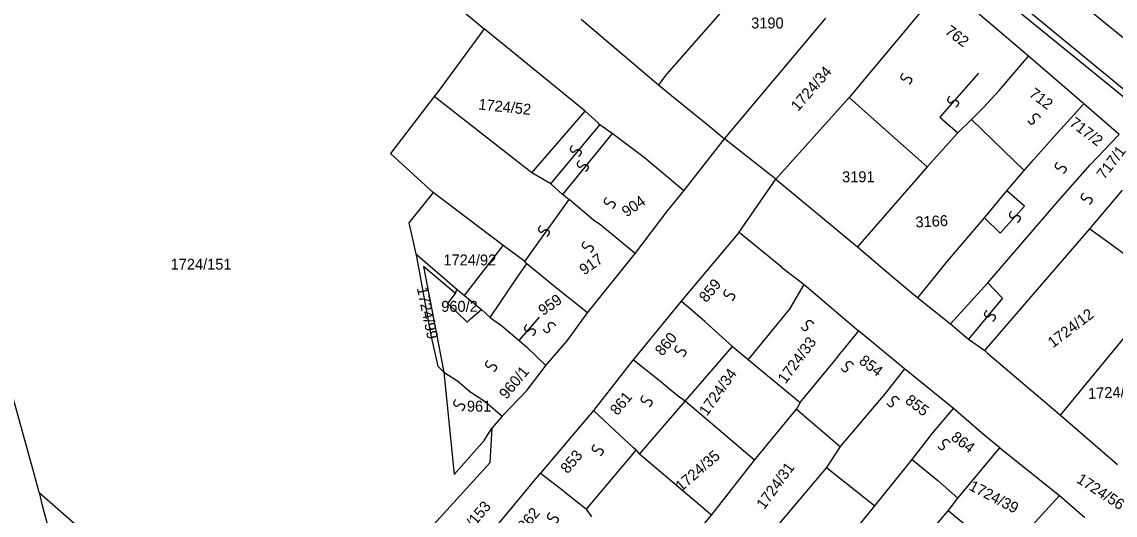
# Model space of a CAD drawing. Extents: x -581999 to -572728, y -1219553 to -1212032.
# Drawn here: x -578552 to -578351.7, y -1215656.3 to -1215566 of the extents above; entities that cross this region are included whole.
import ezdxf

# ---------------------------------------------------------------- set-up
doc = ezdxf.new("R2010")
doc.units = 0
for name, color, linetype in [('Vrstva 1', 7, 'Continuous'), ('Vrstva 2', 7, 'Continuous'), ('Vrstva 4', 7, 'Continuous'), ('Vrstva 6', 7, 'Continuous')]:
    doc.layers.add(name, color=color, linetype=linetype)

msp = doc.modelspace()

# ---------------------------------------------------------------- linework, layer by layer
at = {"layer": 'Vrstva 1'}
for p, q in [((-578500.138, -1215539.76), (-578467.315, -1215567.303)), ((-578430.775, -1215596.918), (-578423.284, -1215587.415)), ((-578413.904, -1215594.804), (-578423.284, -1215587.415)), ((-578420.638, -1215604.474), (-578413.904, -1215594.804)), ((-578470.898, -1215616.085), (-578463.835, -1215606.894)), ((-578472.578, -1215615.681), (-578478.448, -1215610.76)), ((-578478.448, -1215610.76), (-578474.701, -1215630.091)), ((-578473.952, -1215617.555), (-578472.578, -1215615.681)), ((-578472.578, -1215615.681), (-578472.313, -1215614.94)), ((-578470.455, -1215620.953), (-578473.952, -1215617.555)), ((-578469.83, -1215620.367), (-578470.455, -1215620.953)), ((-578469.83, -1215620.367), (-578467.832, -1215618.61)), ((-578474.701, -1215630.091), (-578472.828, -1215648.836)), ((-578467.332, -1215642.627), (-578465.871, -1215640.298)), ((-578472.828, -1215648.836), (-578467.332, -1215642.627)), ((-578548.825, -1215652.118), (-578520.198, -1215677.165))]:
    msp.add_line(p, q, dxfattribs=at)
for points in [[(-578433.992, -1215511.611), (-578315.4, -1215607.929)], [(-578416.974, -1215556.238), (-578433.877, -1215575.53)], [(-578367.591, -1215572.29), (-578383.131, -1215559.047), (-578400.453, -1215579.858)], [(-578449.558, -1215565.489), (-578435.404, -1215577.522)], [(-578423.284, -1215587.415), (-578404.758, -1215565.353)], [(-578448.816, -1215582.341), (-578467.315, -1215567.303), (-578475.737, -1215578.764), (-578476.49, -1215579.668)], [(-578372.982, -1215578.582), (-578367.591, -1215572.29)], [(-578357.461, -1215580.996), (-578367.591, -1215572.29)], [(-578433.877, -1215575.53), (-578435.404, -1215577.522)], [(-578435.404, -1215577.522), (-578432.98, -1215579.481)], [(-578476.49, -1215579.668), (-578484.46, -1215590.07), (-578476.638, -1215597.204)], [(-578458.591, -1215593.643), (-578476.49, -1215579.668)], [(-578432.98, -1215579.481), (-578425.998, -1215585.162)], [(-578413.904, -1215594.804), (-578400.453, -1215579.858)], [(-578400.453, -1215579.858), (-578395.957, -1215583.883)], [(-578375.84, -1215581.698), (-578372.982, -1215578.582)], [(-578458.591, -1215593.643), (-578448.816, -1215582.341)], [(-578446.111, -1215584.816), (-578446.411, -1215584.466), (-578448.816, -1215582.341)], [(-578378.026, -1215583.887), (-578375.84, -1215581.698)], [(-578362.916, -1215586.976), (-578357.461, -1215580.996)], [(-578350.995, -1215586.596), (-578357.461, -1215580.996)], [(-578395.957, -1215583.883), (-578386.17, -1215592.501)], [(-578380.548, -1215586.328), (-578378.026, -1215583.887)], [(-578368.381, -1215593.208), (-578378.026, -1215583.887)], [(-578443.855, -1215586.441), (-578446.111, -1215584.816)], [(-578437.991, -1215590.846), (-578443.855, -1215586.441)], [(-578425.998, -1215585.162), (-578423.284, -1215587.415)], [(-578386.17, -1215592.501), (-578380.548, -1215586.328)], [(-578366.699, -1215591.271), (-578362.916, -1215586.976)], [(-578356.288, -1215592.14), (-578350.995, -1215586.596)], [(-578439.646, -1215608.372), (-578433.733, -1215600.568), (-578430.775, -1215596.918), (-578437.991, -1215590.846)], [(-578368.381, -1215593.208), (-578366.699, -1215591.271)], [(-578362.225, -1215598.896), (-578356.288, -1215592.14)], [(-578455.133, -1215595.62), (-578458.591, -1215593.643)], [(-578386.17, -1215592.501), (-578398.948, -1215607.195)], [(-578371.575, -1215596.914), (-578368.381, -1215593.208)], [(-578452.946, -1215597.566), (-578455.133, -1215595.62)], [(-578413.904, -1215594.804), (-578398.948, -1215607.195)], [(-578476.638, -1215597.204), (-578481.15, -1215602.781), (-578479.832, -1215608.428)], [(-578459.898, -1215609.832), (-578463.835, -1215606.894), (-578476.638, -1215597.204)], [(-578451.778, -1215598.525), (-578451.824, -1215598.504), (-578452.946, -1215597.566)], [(-578375.694, -1215601.883), (-578371.575, -1215596.914)], [(-578356.379, -1215603.882), (-578350.411, -1215596.807)], [(-578447.314, -1215602.298), (-578451.778, -1215598.525)], [(-578375.034, -1215613.782), (-578362.225, -1215598.896)], [(-578445.96, -1215603.21), (-578447.314, -1215602.298)], [(-578382.419, -1215609.8), (-578375.694, -1215601.883)], [(-578439.646, -1215608.372), (-578445.96, -1215603.21)], [(-578420.638, -1215604.474), (-578431.218, -1215617.089)], [(-578420.638, -1215604.474), (-578412.976, -1215610.706)], [(-578375.627, -1215626.112), (-578356.379, -1215603.882)], [(-578356.379, -1215603.882), (-578353.295, -1215606.06)], [(-578353.295, -1215606.06), (-578342.033, -1215614.305)], [(-578479.832, -1215608.428), (-578479.645, -1215609.287), (-578477.045, -1215623.657)], [(-578479.832, -1215608.428), (-578472.313, -1215614.94), (-578470.898, -1215616.085), (-578467.832, -1215618.61), (-578466.213, -1215620.086)], [(-578448.367, -1215619.221), (-578439.646, -1215608.372)], [(-578398.948, -1215607.195), (-578391.89, -1215613.133)], [(-578461.186, -1215612.62), (-578459.493, -1215610.265)], [(-578459.493, -1215610.265), (-578459.898, -1215609.832)], [(-578454.381, -1215614.515), (-578459.493, -1215610.265)], [(-578387.858, -1215616.527), (-578382.419, -1215609.8)], [(-578412.976, -1215610.706), (-578412.88, -1215610.899), (-578408.687, -1215614.086)], [(-578466.213, -1215620.086), (-578461.186, -1215612.62)], [(-578411.227, -1215618.329), (-578408.687, -1215614.086)], [(-578408.687, -1215614.086), (-578398.751, -1215622.529)], [(-578391.89, -1215613.133), (-578387.858, -1215616.527)], [(-578381.895, -1215621.278), (-578375.034, -1215613.782)], [(-578448.367, -1215619.221), (-578454.381, -1215614.515)], [(-578431.218, -1215617.089), (-578440.052, -1215627.839)], [(-578426.791, -1215620.946), (-578426.881, -1215620.826), (-578431.218, -1215617.089)], [(-578411.227, -1215618.329), (-578418.968, -1215627.765)], [(-578387.858, -1215616.527), (-578381.895, -1215621.278)], [(-578466.213, -1215620.086), (-578464.103, -1215621.634)], [(-578452.126, -1215624.345), (-578448.367, -1215619.221)], [(-578361.77, -1215637.944), (-578346.992, -1215620.03)], [(-578464.103, -1215621.634), (-578460.887, -1215624.314)], [(-578421.805, -1215625.415), (-578426.791, -1215620.946)], [(-578381.895, -1215621.278), (-578378.619, -1215624.077)], [(-578477.045, -1215623.657), (-578475.842, -1215629.03)], [(-578460.887, -1215624.314), (-578459.52, -1215625.53)], [(-578455.998, -1215628.886), (-578455.661, -1215628.454), (-578452.126, -1215624.345)], [(-578398.751, -1215622.529), (-578401.923, -1215626.442)], [(-578390.349, -1215629.458), (-578398.751, -1215622.529)], [(-578378.619, -1215624.077), (-578375.627, -1215626.112)], [(-578459.52, -1215625.53), (-578455.998, -1215628.886)], [(-578430.479, -1215635.378), (-578421.805, -1215625.415)], [(-578421.805, -1215625.415), (-578418.968, -1215627.765)], [(-578402.554, -1215627.309), (-578401.923, -1215626.442)], [(-578375.627, -1215626.112), (-578375.091, -1215626.623), (-578361.77, -1215637.944)], [(-578440.052, -1215627.839), (-578440.105, -1215627.903), (-578447.3, -1215637.127)], [(-578435.242, -1215631.633), (-578440.052, -1215627.839)], [(-578418.968, -1215627.765), (-578409.433, -1215635.663)], [(-578409.433, -1215635.663), (-578402.554, -1215627.309)], [(-578549.791, -1215648.685), (-578554.939, -1215629.971)], [(-578475.842, -1215629.03), (-578474.701, -1215630.091), (-578472.224, -1215631.71), (-578469.955, -1215633.606)], [(-578459.522, -1215633.454), (-578456.336, -1215629.318), (-578455.998, -1215628.886)], [(-578390.349, -1215629.458), (-578393.879, -1215634.007)], [(-578381.362, -1215636.753), (-578390.349, -1215629.458)], [(-578431.978, -1215634.348), (-578435.242, -1215631.633)], [(-578469.955, -1215633.606), (-578467.158, -1215635.445)], [(-578464.022, -1215638.123), (-578459.522, -1215633.454)], [(-578430.479, -1215635.378), (-578431.978, -1215634.348)], [(-578393.879, -1215634.007), (-578402.118, -1215643.725)], [(-578467.158, -1215635.445), (-578464.022, -1215638.123)], [(-578438.838, -1215645.129), (-578430.479, -1215635.378)], [(-578417.794, -1215646.219), (-578430.479, -1215635.378)], [(-578409.433, -1215635.663), (-578410.099, -1215636.856)], [(-578464.022, -1215638.123), (-578465.871, -1215640.298)], [(-578447.3, -1215637.127), (-578457.033, -1215648.576)], [(-578443.394, -1215640.765), (-578447.3, -1215637.127)], [(-578417.794, -1215646.219), (-578410.099, -1215636.856)], [(-578410.099, -1215636.856), (-578402.118, -1215643.725), (-578404.641, -1215647.517)], [(-578385.186, -1215641.267), (-578381.362, -1215636.753)], [(-578375.819, -1215641.585), (-578381.362, -1215636.753)], [(-578361.77, -1215637.944), (-578351.276, -1215647.014)], [(-578466.233, -1215646.632), (-578465.871, -1215640.298)], [(-578439.949, -1215643.973), (-578443.394, -1215640.765)], [(-578388.926, -1215646.1), (-578385.186, -1215641.267)], [(-578372.88, -1215643.96), (-578375.819, -1215641.585)], [(-578448.57, -1215655.195), (-578439.472, -1215644.383)], [(-578439.472, -1215644.383), (-578439.949, -1215643.973)], [(-578439.472, -1215644.383), (-578438.838, -1215645.129)], [(-578380.528, -1215653.138), (-578372.88, -1215643.96)], [(-578372.88, -1215643.96), (-578361.914, -1215652.667)], [(-578425.696, -1215656.242), (-578438.838, -1215645.129)], [(-578425.696, -1215656.242), (-578417.794, -1215646.219)], [(-578395.737, -1215654.556), (-578388.926, -1215646.1)], [(-578388.926, -1215646.1), (-578384.223, -1215649.917)], [(-578505.444, -1215689.656), (-578466.233, -1215646.632)], [(-578404.641, -1215647.517), (-578419.174, -1215664.753)], [(-578404.641, -1215647.517), (-578395.737, -1215654.556)], [(-578548.825, -1215652.118), (-578549.791, -1215648.685)], [(-578464.93, -1215658.171), (-578457.033, -1215648.576)], [(-578457.033, -1215648.576), (-578452.869, -1215651.777)], [(-578384.223, -1215649.917), (-578380.528, -1215653.138)], [(-578548.825, -1215652.118), (-578548.268, -1215654.522)], [(-578452.869, -1215651.777), (-578452.589, -1215651.992), (-578451.525, -1215652.843)], [(-578548.268, -1215654.522), (-578541.777, -1215678.287)], [(-578451.525, -1215652.843), (-578448.57, -1215655.195)], [(-578410.354, -1215672.55), (-578395.737, -1215654.556)], [(-578382.326, -1215655.469), (-578380.528, -1215653.138)], [(-578361.914, -1215652.667), (-578370.219, -1215661.774)], [(-578361.914, -1215652.667), (-578357.361, -1215656.607), (-578357.297, -1215656.65)], [(-578447.614, -1215656.557), (-578448.57, -1215655.195)], [(-578427.203, -1215658.118), (-578425.696, -1215656.242)], [(-578390.134, -1215664.627), (-578382.326, -1215655.469)], [(-578371.999, -1215663.946), (-578382.326, -1215655.469)]]:
    msp.add_lwpolyline(points, dxfattribs=at)
at = {"layer": 'Vrstva 4'}
for points in [[(-578479.233, -1215472.341), (-578312.417, -1215609.28)], [(-578421.464, -1215511.032), (-578303.071, -1215607.158)], [(-578376.751, -1215575.377), (-578383.826, -1215583.434), (-578380.548, -1215586.328)], [(-578455.133, -1215595.62), (-578446.111, -1215584.816)], [(-578443.855, -1215586.441), (-578452.946, -1215597.566)], [(-578375.694, -1215601.883), (-578372.81, -1215604.663), (-578368.355, -1215599.753), (-578371.575, -1215596.914)], [(-578459.898, -1215609.832), (-578451.778, -1215598.525)], [(-578375.034, -1215613.782), (-578372.37, -1215616.529), (-578378.619, -1215624.077)], [(-578460.887, -1215624.314), (-578457.188, -1215620.042)]]:
    msp.add_lwpolyline(points, dxfattribs=at)
at = {"layer": 'Vrstva 6'}
for points in [[(-578390.591, -1215575.374), (-578391.178, -1215575.996), (-578390.723, -1215576.605), (-578390.317, -1215576.593), (-578390.031, -1215576.288), (-578389.725, -1215576.134), (-578389.425, -1215576.15), (-578389.218, -1215576.252), (-578389.042, -1215576.455), (-578388.997, -1215576.819), (-578389.332, -1215577.331), (-578389.49, -1215577.423)], [(-578382.011, -1215579.585), (-578382.598, -1215580.207), (-578382.143, -1215580.816), (-578381.737, -1215580.804), (-578381.451, -1215580.499), (-578381.145, -1215580.345), (-578380.845, -1215580.361), (-578380.638, -1215580.463), (-578380.462, -1215580.666), (-578380.417, -1215581.03), (-578380.752, -1215581.542), (-578380.91, -1215581.634)], [(-578367.719, -1215584.113), (-578367.239, -1215584.82), (-578366.545, -1215584.509), (-578366.468, -1215584.109), (-578366.704, -1215583.764), (-578366.789, -1215583.432), (-578366.707, -1215583.142), (-578366.563, -1215582.962), (-578366.327, -1215582.834), (-578365.962, -1215582.87), (-578365.535, -1215583.309), (-578365.48, -1215583.482)], [(-578451.134, -1215588.602), (-578451.721, -1215589.224), (-578451.266, -1215589.833), (-578450.86, -1215589.821), (-578450.574, -1215589.516), (-578450.268, -1215589.362), (-578449.968, -1215589.378), (-578449.761, -1215589.48), (-578449.585, -1215589.683), (-578449.54, -1215590.047), (-578449.875, -1215590.559), (-578450.033, -1215590.651)], [(-578449.856, -1215591.348), (-578450.443, -1215591.97), (-578449.988, -1215592.579), (-578449.582, -1215592.567), (-578449.296, -1215592.262), (-578448.99, -1215592.108), (-578448.69, -1215592.124), (-578448.483, -1215592.226), (-578448.307, -1215592.429), (-578448.262, -1215592.793), (-578448.597, -1215593.305), (-578448.755, -1215593.397)], [(-578362.297, -1215591.669), (-578362.884, -1215592.291), (-578362.429, -1215592.9), (-578362.023, -1215592.888), (-578361.737, -1215592.583), (-578361.431, -1215592.429), (-578361.131, -1215592.445), (-578360.924, -1215592.547), (-578360.748, -1215592.75), (-578360.703, -1215593.114), (-578361.038, -1215593.626), (-578361.196, -1215593.718)], [(-578444.927, -1215598.123), (-578445.514, -1215598.745), (-578445.059, -1215599.354), (-578444.653, -1215599.342), (-578444.367, -1215599.037), (-578444.061, -1215598.883), (-578443.761, -1215598.899), (-578443.554, -1215599.001), (-578443.378, -1215599.204), (-578443.333, -1215599.568), (-578443.668, -1215600.08), (-578443.826, -1215600.172)], [(-578357.551, -1215597.345), (-578358.138, -1215597.967), (-578357.683, -1215598.576), (-578357.277, -1215598.564), (-578356.991, -1215598.259), (-578356.685, -1215598.105), (-578356.385, -1215598.121), (-578356.178, -1215598.223), (-578356.002, -1215598.426), (-578355.957, -1215598.79), (-578356.292, -1215599.302), (-578356.45, -1215599.394)], [(-578370.694, -1215600.64), (-578371.281, -1215601.262), (-578370.826, -1215601.871), (-578370.42, -1215601.859), (-578370.134, -1215601.554), (-578369.828, -1215601.4), (-578369.528, -1215601.416), (-578369.321, -1215601.518), (-578369.145, -1215601.721), (-578369.1, -1215602.085), (-578369.435, -1215602.597), (-578369.593, -1215602.689)], [(-578456.975, -1215603.249), (-578457.562, -1215603.871), (-578457.107, -1215604.48), (-578456.701, -1215604.468), (-578456.415, -1215604.163), (-578456.109, -1215604.009), (-578455.809, -1215604.025), (-578455.602, -1215604.127), (-578455.426, -1215604.33), (-578455.381, -1215604.694), (-578455.716, -1215605.206), (-578455.874, -1215605.298)], [(-578448.943, -1215606.178), (-578449.53, -1215606.8), (-578449.075, -1215607.409), (-578448.669, -1215607.397), (-578448.383, -1215607.092), (-578448.077, -1215606.938), (-578447.777, -1215606.954), (-578447.57, -1215607.056), (-578447.394, -1215607.259), (-578447.349, -1215607.623), (-578447.684, -1215608.135), (-578447.842, -1215608.227)], [(-578423.022, -1215614.967), (-578423.609, -1215615.589), (-578423.154, -1215616.198), (-578422.748, -1215616.186), (-578422.462, -1215615.881), (-578422.156, -1215615.727), (-578421.856, -1215615.743), (-578421.649, -1215615.845), (-578421.473, -1215616.048), (-578421.428, -1215616.412), (-578421.763, -1215616.924), (-578421.921, -1215617.016)], [(-578375.257, -1215618.766), (-578375.844, -1215619.388), (-578375.389, -1215619.997), (-578374.983, -1215619.985), (-578374.697, -1215619.68), (-578374.391, -1215619.526), (-578374.091, -1215619.542), (-578373.884, -1215619.644), (-578373.708, -1215619.847), (-578373.663, -1215620.211), (-578373.998, -1215620.723), (-578374.156, -1215620.815)], [(-578459.53, -1215621.374), (-578460.117, -1215621.996), (-578459.662, -1215622.605), (-578459.256, -1215622.593), (-578458.97, -1215622.288), (-578458.664, -1215622.134), (-578458.364, -1215622.15), (-578458.157, -1215622.252), (-578457.981, -1215622.455), (-578457.936, -1215622.819), (-578458.271, -1215623.331), (-578458.429, -1215623.423)], [(-578456.514, -1215622.258), (-578456.034, -1215622.965), (-578455.34, -1215622.654), (-578455.263, -1215622.254), (-578455.499, -1215621.909), (-578455.584, -1215621.577), (-578455.502, -1215621.287), (-578455.358, -1215621.107), (-578455.122, -1215620.979), (-578454.757, -1215621.015), (-578454.33, -1215621.454), (-578454.275, -1215621.627)], [(-578409.236, -1215621.891), (-578408.756, -1215622.598), (-578408.062, -1215622.287), (-578407.985, -1215621.887), (-578408.221, -1215621.542), (-578408.306, -1215621.21), (-578408.224, -1215620.92), (-578408.08, -1215620.74), (-578407.844, -1215620.612), (-578407.479, -1215620.648), (-578407.052, -1215621.087), (-578406.997, -1215621.26)], [(-578431.967, -1215625.22), (-578432.554, -1215625.842), (-578432.099, -1215626.451), (-578431.693, -1215626.439), (-578431.407, -1215626.134), (-578431.101, -1215625.98), (-578430.801, -1215625.996), (-578430.594, -1215626.098), (-578430.418, -1215626.301), (-578430.373, -1215626.665), (-578430.708, -1215627.177), (-578430.866, -1215627.269)], [(-578466.649, -1215627.966), (-578467.236, -1215628.588), (-578466.781, -1215629.197), (-578466.375, -1215629.185), (-578466.089, -1215628.88), (-578465.783, -1215628.726), (-578465.483, -1215628.742), (-578465.276, -1215628.844), (-578465.1, -1215629.047), (-578465.055, -1215629.411), (-578465.39, -1215629.923), (-578465.548, -1215630.015)], [(-578401.935, -1215629.398), (-578401.455, -1215630.105), (-578400.761, -1215629.794), (-578400.684, -1215629.394), (-578400.92, -1215629.049), (-578401.005, -1215628.717), (-578400.923, -1215628.427), (-578400.779, -1215628.247), (-578400.543, -1215628.119), (-578400.178, -1215628.155), (-578399.751, -1215628.594), (-578399.696, -1215628.767)], [(-578438.173, -1215634.374), (-578438.76, -1215634.996), (-578438.305, -1215635.605), (-578437.899, -1215635.593), (-578437.613, -1215635.288), (-578437.307, -1215635.134), (-578437.007, -1215635.15), (-578436.8, -1215635.252), (-578436.624, -1215635.455), (-578436.579, -1215635.819), (-578436.914, -1215636.331), (-578437.072, -1215636.423)], [(-578472.491, -1215635.106), (-578473.078, -1215635.728), (-578472.623, -1215636.337), (-578472.217, -1215636.325), (-578471.931, -1215636.02), (-578471.625, -1215635.866), (-578471.325, -1215635.882), (-578471.118, -1215635.984), (-578470.942, -1215636.187), (-578470.897, -1215636.551), (-578471.232, -1215637.063), (-578471.39, -1215637.155)], [(-578393.538, -1215635.806), (-578393.058, -1215636.513), (-578392.364, -1215636.202), (-578392.287, -1215635.802), (-578392.523, -1215635.457), (-578392.608, -1215635.125), (-578392.526, -1215634.835), (-578392.382, -1215634.655), (-578392.146, -1215634.527), (-578391.781, -1215634.563), (-578391.354, -1215635.002), (-578391.299, -1215635.175)], [(-578384.229, -1215643.679), (-578383.749, -1215644.386), (-578383.055, -1215644.075), (-578382.978, -1215643.675), (-578383.214, -1215643.33), (-578383.299, -1215642.998), (-578383.217, -1215642.708), (-578383.073, -1215642.528), (-578382.837, -1215642.4), (-578382.472, -1215642.436), (-578382.045, -1215642.875), (-578381.99, -1215643.048)], [(-578447.118, -1215643.346), (-578447.705, -1215643.968), (-578447.25, -1215644.577), (-578446.844, -1215644.565), (-578446.558, -1215644.26), (-578446.252, -1215644.106), (-578445.952, -1215644.122), (-578445.745, -1215644.224), (-578445.569, -1215644.427), (-578445.524, -1215644.791), (-578445.859, -1215645.303), (-578446.017, -1215645.395)], [(-578455.331, -1215655.795), (-578455.918, -1215656.417), (-578455.463, -1215657.026), (-578455.057, -1215657.014), (-578454.771, -1215656.709), (-578454.465, -1215656.555), (-578454.165, -1215656.571), (-578453.958, -1215656.673), (-578453.782, -1215656.876), (-578453.737, -1215657.24), (-578454.072, -1215657.752), (-578454.23, -1215657.844)]]:
    msp.add_open_spline(points, degree=2, dxfattribs=at)

# ---------------------------------------------------------------- texts
at = {"layer": 'Vrstva 2'}
for s, p in [('3190', (-578418.412, -1215567.208)), ('3191', (-578401.754, -1215595.345)), ('1724/92', (-578474.786, -1215610.564)), ('1724/151', (-578524.764, -1215611.346)), ('960/2', (-578475.192, -1215619.053)), ('961', (-578470.491, -1215637.315))]:
    msp.add_text(s, height=2, dxfattribs=at).set_placement(p)
for s, rotation, p in [('762', 322.6958, (-578383.062, -1215568.036)), ('1724/34', 49.23997, (-578409.822, -1215582.515)), ('712', 322.6958, (-578367.653, -1215579.484)), ('1724/52', 353.94389, (-578468.454, -1215582.029)), ('717/2', 322.6958, (-578360.261, -1215584.823)), ('717/1', 52.6958, (-578353.708, -1215594.972)), ('904', 34.729, (-578441.232, -1215601.803)), ('3166', 2.95684, (-578388.263, -1215603.644)), ('917', 34.729, (-578449.003, -1215612.418)), ('859', 50.29423, (-578426.624, -1215617.496)), ('1724/99', 281.83849, (-578479.671, -1215614.728)), ('959', 34.729, (-578456.543, -1215619.851)), ('1724/12', 37.40235, (-578363.126, -1215625.754)), ('860', 50.29423, (-578434.696, -1215627.286)), ('1724/33', 53.51207, (-578412.106, -1215632.351)), ('854', 323.04609, (-578398.819, -1215628.373)), ('960/1', 50.15687, (-578463.248, -1215635.195)), ('1724/34', 54.86121, (-578426.495, -1215638.246)), ('1724/102', 2.95684, (-578356.642, -1215635.017)), ('861', 50.29423, (-578442.917, -1215638.14)), ('855', 323.04609, (-578390.372, -1215635.597)), ('864', 323.04609, (-578381.961, -1215642.357)), ('853', 50.29423, (-578452.003, -1215648.811)), ('1724/35', 41.09485, (-578431.23, -1215652.049)), ('1724/31', 54.0957, (-578416.028, -1215655.355)), ('1724/39', 332.41942, (-578378.675, -1215651.547)), ('1724/56', 327.11464, (-578358.966, -1215650.157)), ('1724/153', 50.15687, (-578473.097, -1215663.289)), ('862', 50.29423, (-578459.842, -1215659.351))]:
    msp.add_text(s, height=2, rotation=rotation, dxfattribs=at).set_placement(p)

doc.saveas('drawing.dxf')
